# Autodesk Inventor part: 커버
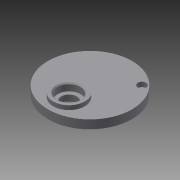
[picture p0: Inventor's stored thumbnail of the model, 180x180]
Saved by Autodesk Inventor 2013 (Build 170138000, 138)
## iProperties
Created: 2015-07
Part Number: 커버
Material: 일반
Document SubType Name: Modeling
Designer: user
Density: 1 g/cm^3
Author: user
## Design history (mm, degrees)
sketch "스케치1"
  geometry: C1 r 40 at (0, 0); 1 further point
  constraints: 1 centre point, 1 coincident
  dimensions: "d0" = 40 radius of C1
extrude "돌출1" new body sketch "스케치1" distance "d1" = 9; taper "d2" = 0 deg
sketch "스케치2"
  geometry: L1 (0, 0)-(0, -20); C1 r 40 at (0, 0) reference; C2 r 15 at (0, -20)
  constraints: 2 end point, 1 centre point, 1 coincident, 1 vertical
  dimensions: "d3" = 20 distance of L1.start L1.end; "d4" = 15 radius of C2
extrude "돌출2" join sketch "스케치2" distance "d5" = 4; taper "d6" = 0 deg
sketch "스케치3"
  geometry: C1 r 15 at (0, 0) reference; C2 r 11 at (0, 0); 1 further point
  constraints: 1 centre point, 1 coincident
  dimensions: "d7" = 11 radius of C2
extrude "돌출3" cut sketch "스케치3" distance "d8" = 7; taper "d9" = 0 deg
sketch "스케치4"
  geometry: L1 (0, 0)-(0, 11); L2 (0, 0)-(0, -20); C1 r 40 at (0, 0) reference; C2 r 14 at (0, 11); C3 r 14 at (0, -20)
  constraints: 4 end point, 2 centre point, 2 coincident, 1 collinear, 1 vertical
  dimensions: "d10" = 11 distance of L1.start L1.end; "d11" = 14 radius of C2; "d12" = 20 distance of L1.start L2.end; "d13" = 14 radius of C3
extrude "돌출4" join sketch "스케치4" distance "d14" = 3; taper "d15" = 0 deg
sketch "스케치5"
  geometry: C1 r 14 at (0, 0) reference; C2 r 11 at (0, 0); 1 further point
  constraints: 1 centre point, 1 coincident
  dimensions: "d16" = 11 radius of C2
extrude "돌출5" cut sketch "스케치5" distance "d17" = 7; taper "d18" = 0 deg
sketch "스케치6"
  geometry: C1 r 11 at (0, 0) reference; C2 r 7.5 at (0, 0); 1 further point
  constraints: 1 centre point, 1 coincident
  dimensions: "d19" = 7.5 radius of C2
extrude "돌출6" cut sketch "스케치6" distance "d20" = 2; taper "d21" = 0 deg
sketch "스케치7"
  geometry: C1 r 14 at (0, 0) reference; C2 r 11 at (0, 0); 1 further point
  constraints: 1 centre point, 1 coincident
  dimensions: "d22" = 11 radius of C2
extrude "돌출7" cut sketch "스케치7" distance "d23" = 7; taper "d24" = 0 deg
sketch "스케치8"
  geometry: C1 r 9 at (0, 0); 2 further points
  constraints: 1 centre point, 1 coincident, 1 vertical alignment
  dimensions: "d25" = 9 radius of C1
extrude "돌출8" cut sketch "스케치8" distance "d26" = 1; taper "d27" = 0 deg
chamfer "모따기1" distance "d28" = 1; stored, may be unused: second distance "d29" = 2, angle "d30" = 45 deg
chamfer "모따기2" distance "d31" = 1; stored, may be unused: second distance "d32" = 2, angle "d33" = 45 deg
fillet "모깎기1" dims "d34" = 0.3
sketch "스케치9"
  geometry: L1 (0, 0)-(0, 35); L2 (0, 0)-(24.749, 24.749); C1 r 40 at (0, 0) reference; A1 r 35 centre (0, 0) between (0, 35) and (24.749, 24.749)
  constraints: 4 end point, 2 point on circle, 1 centre point, 1 coincident, 1 vertical
  dimensions: "d35" = 35 radius of A1; "d36" = 45 deg angle of L2 L1
hole "구멍1" sketch "스케치9" at (24.749, 24.749) diameter "d38" = 4.5; stored, may be unused: countersink angle "d42" = 90 deg, drill point angle "d44" = 118 deg; dims "d39" = 6, "d40" = 8, "d41" = 4.4, "d43" = 8
node "솔리드1"
